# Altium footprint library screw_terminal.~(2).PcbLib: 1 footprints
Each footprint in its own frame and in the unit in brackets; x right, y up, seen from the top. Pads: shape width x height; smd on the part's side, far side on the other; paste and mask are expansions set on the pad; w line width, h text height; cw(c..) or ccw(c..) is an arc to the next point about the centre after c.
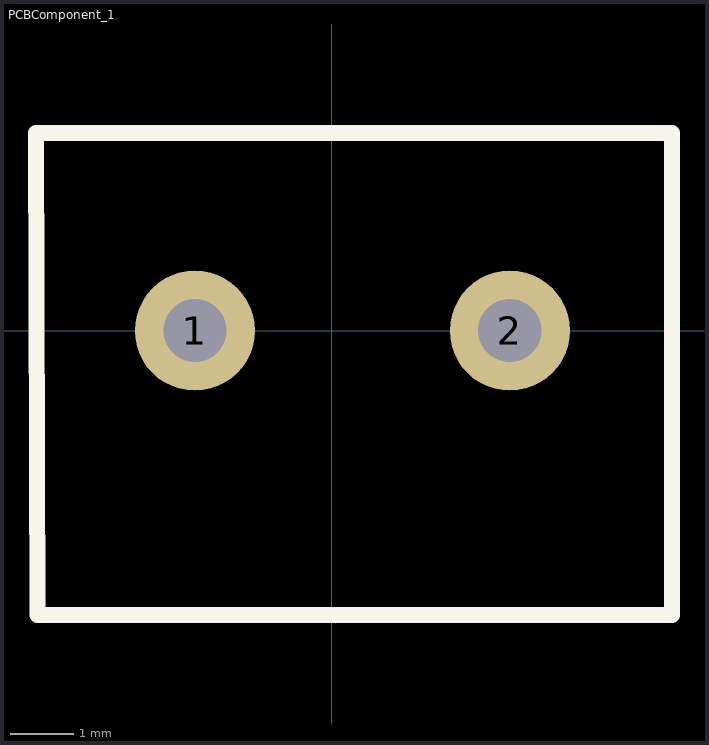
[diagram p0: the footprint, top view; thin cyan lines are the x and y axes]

## PCBComponent_1 [mm]
pads (2):
  round 1.9 hole 1: 1(-2.159,0) 2(2.819,0)
Top Overlay:
  lines w0.254: -4.674,3.124 5.385,3.124 5.385,-4.496 -4.648,-4.496 -4.674,3.124
3D body: height 10, standoff 0, extent -4.521,-4.343 5.232,2.997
